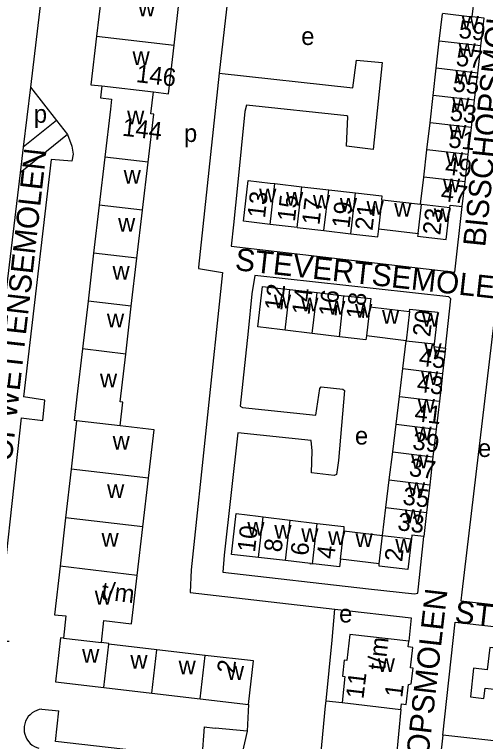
# Model space of a CAD drawing. Extents: x 159902 to 161769, y 383692 to 384875.
# Drawn here: x 161287.3 to 161393, y 384324.5 to 384487.6 of the extents above; entities that cross this region are included whole.
import ezdxf

# ---------------------------------------------------------------- set-up
doc = ezdxf.new("R2010")
doc.units = 0
for name, color, linetype in [('BLT_Basislijn', 7, 'Continuous'), ('BLT_Bebouwing', 7, 'Continuous'), ('BLT_Centroide', 7, 'Continuous'), ('BLT_Huisnummer', 7, 'Continuous'), ('BLT_Huisnummer_ tussenligend', 7, 'Continuous'), ('BLT_Huisnummer_reeks', 7, 'Continuous'), ('BLT_Onderverdeling_panden', 7, 'Continuous'), ('BLT_Straatnaam', 7, 'Continuous')]:
    doc.layers.add(name, color=color, linetype=linetype)

msp = doc.modelspace()

# ---------------------------------------------------------------- linework, layer by layer
at = {"layer": 'BLT_Basislijn'}
for p, q in [((161294.24, 384500), (161290.85, 384471.28)), ((161336.09, 384500), (161333.26, 384474.42)), ((161290.85, 384471.28), (161289.23, 384457.8)), ((161290.85, 384471.28), (161296.72, 384463.85)), ((161296.72, 384463.85), (161289.23, 384457.8)), ((161296.72, 384463.85), (161299.15, 384460.67)), ((161299.15, 384460.67), (161288.54, 384452.1)), ((161289.23, 384457.8), (161288.54, 384452.1)), ((161288.54, 384452.1), (161273.96, 384331.2)), ((161357.23, 384333.57), (161360.85, 384333.19)), ((161293.42, 384331.7), (161297.23, 384331.31)), ((161339.78, 384332.77), (161339.49, 384326.74)), ((161374.02, 384331.65), (161372.88, 384319.36)), ((161329.87, 384327.74), (161332.36, 384327.45)), ((161339.49, 384326.74), (161332.36, 384327.45)), ((161339.49, 384326.74), (161337.1, 384316.46)), ((161383.46, 384325.86), (161380.67, 384301.54)), ((161463.15, 384317.18), (161383.46, 384325.86))]:
    msp.add_line(p, q, dxfattribs=at)
for points in [[(161333.26, 384474.42), (161363.22, 384471.15), (161364.07, 384477.37), (161369.81, 384476.8), (161367.82, 384457.29), (161361.86, 384458.02), (161362.1, 384464.71), (161361.87, 384464.87), (161339.39, 384467.22), (161339.01, 384465.84), (161337.35, 384449.24), (161336.45, 384440.43), (161335.9, 384435.6), (161386.14, 384429.8), (161387.8, 384444.54)], [(161333.26, 384474.42), (161328.56, 384430.9), (161328.61, 384430.62), (161333.96, 384429.73), (161326.96, 384362.94), (161326.68, 384357.85), (161359.22, 384354.18)], [(161299.15, 384460.67), (161300.15, 384458.09), (161300.4, 384456.26), (161300.15, 384454.68), (161295.53, 384455.04), (161289.27, 384401.76)], [(161384.08, 384412.74), (161385.23, 384423.82), (161384.82, 384424.26), (161368.51, 384426.04), (161341.23, 384429.03), (161340.6, 384424.91), (161339.73, 384416.53), (161337.97, 384399.67), (161338.45, 384399.39), (161354.91, 384397.69), (161355.81, 384403.7), (161356.13, 384404.02), (161361, 384403.52), (161361.38, 384403.23), (161360.03, 384387.49), (161359.59, 384384.34), (161359.04, 384384.15), (161353.94, 384384.73), (161354.15, 384389.69), (161353.89, 384392.01), (161337.42, 384393.73), (161334.37, 384366.25), (161334.03, 384362.42), (161366.79, 384358.72), (161377.06, 384357.55), (161377.85, 384357.74), (161379.17, 384370.48)], [(161459.19, 384412.99), (161459.41, 384415.65), (161437.91, 384418.21), (161395.42, 384422.86), (161387.74, 384357.97), (161387.49, 384355.98), (161488.9, 384344.6)], [(161288.75, 384397.06), (161293.59, 384396.45), (161294.07, 384401.08), (161289.27, 384401.76)], [(161288.75, 384397.06), (161283.22, 384346.97), (161286.06, 384346.97)], [(161357.23, 384333.57), (161358.6, 384347.17), (161359.22, 384354.18)], [(161359.22, 384354.18), (161376.36, 384352.21), (161375.82, 384346.94)], [(161383.46, 384325.86), (161386.25, 384351.26), (161481.08, 384340.63)], [(161372.88, 384319.36), (161356.05, 384321.28), (161357.12, 384332.46), (161357.23, 384333.57)], [(161293.42, 384331.7), (161292.83, 384331.6), (161292.26, 384331.42), (161291.72, 384331.17), (161291.21, 384330.85), (161290.76, 384330.46), (161290.36, 384330.02), (161290.02, 384329.52), (161289.76, 384328.99), (161289.56, 384328.43), (161289.44, 384327.84), (161289.4, 384327.24), (161289.45, 384326.65), (161289.57, 384326.06), (161289.77, 384325.5), (161290.04, 384324.97), (161290.38, 384324.48), (161290.78, 384324.03), (161291.24, 384323.65), (161291.74, 384323.33), (161292.29, 384323.08), (161292.73, 384322.94)], [(161329.87, 384327.74), (161329.33, 384320.72), (161296.47, 384324.43), (161297.23, 384331.31)]]:
    msp.add_lwpolyline(points, dxfattribs=at)
at = {"layer": 'BLT_Bebouwing'}
for p, q in [((161390.06, 384487.11), (161390.96, 384494.84)), ((161306.96, 384493.63), (161305.69, 384482.74)), ((161323.09, 384480.71), (161324.36, 384491.6)), ((161382.67, 384481.64), (161383.37, 384487.74)), ((161381.97, 384475.53), (161382.67, 384481.64)), ((161381.28, 384469.43), (161381.97, 384475.53)), ((161390.59, 384468.36), (161391.31, 384474.47)), ((161317.9, 384465.28), (161318.47, 384470.21)), ((161380.58, 384463.32), (161381.28, 384469.43)), ((161389.88, 384462.26), (161390.59, 384468.36)), ((161308.8, 384466.34), (161307.55, 384455.58)), ((161379.88, 384457.21), (161380.58, 384463.32)), ((161389.16, 384456.15), (161389.88, 384462.26)), ((161379.18, 384451.11), (161379.88, 384457.21)), ((161307.55, 384455.58), (161306.29, 384444.82)), ((161388.45, 384450.05), (161389.16, 384456.15)), ((161316.01, 384443.69), (161317.27, 384454.45)), ((161378.48, 384445), (161379.18, 384451.11)), ((161345.76, 384449.65), (161351.8, 384448.96)), ((161351.8, 384448.96), (161357.84, 384448.27)), ((161387.8, 384444.54), (161388.45, 384450.05)), ((161357.84, 384448.27), (161363.88, 384447.58)), ((161369.85, 384445.99), (161378.48, 384445)), ((161306.29, 384444.82), (161305.04, 384434.06)), ((161314.75, 384432.93), (161316.01, 384443.69)), ((161350.73, 384439.77), (161344.69, 384440.45)), ((161350.73, 384439.77), (161356.77, 384439.09)), ((161356.77, 384439.09), (161362.82, 384438.41)), ((161369.09, 384439.48), (161377.9, 384438.44)), ((161305.04, 384434.06), (161303.78, 384423.3)), ((161313.5, 384422.16), (161314.75, 384432.93)), ((161349.13, 384425.86), (161355.24, 384425.18)), ((161355.24, 384425.18), (161361.26, 384424.5)), ((161361.26, 384424.5), (161361.35, 384424.49)), ((161361.35, 384424.49), (161367.27, 384423.83)), ((161303.78, 384423.3), (161302.52, 384412.54)), ((161367.27, 384423.83), (161367.05, 384421.97)), ((161312.24, 384411.4), (161313.5, 384422.16)), ((161367.05, 384421.97), (161376, 384420.93)), ((161354.13, 384416.02), (161348.03, 384416.76)), ((161360.23, 384415.28), (161354.13, 384416.02)), ((161375.24, 384414.38), (161366.29, 384415.47)), ((161374.48, 384408.14), (161375.24, 384414.38)), ((161302.52, 384412.54), (161301.27, 384401.77)), ((161310.99, 384400.64), (161312.24, 384411.4)), ((161384.08, 384412.74), (161383.41, 384407.05)), ((161373.72, 384401.9), (161374.48, 384408.14)), ((161301.27, 384401.77), (161300.65, 384396.5)), ((161372.96, 384395.66), (161373.72, 384401.9)), ((161382.68, 384400.81), (161381.96, 384394.56)), ((161301.21, 384396.43), (161299.97, 384385.54)), ((161301.21, 384396.43), (161300.65, 384396.5)), ((161372.2, 384389.42), (161372.96, 384395.66)), ((161381.96, 384394.56), (161381.24, 384388.32)), ((161371.44, 384383.18), (161372.2, 384389.42)), ((161381.24, 384388.32), (161380.51, 384382.07)), ((161299.97, 384385.54), (161298.73, 384374.65)), ((161316.11, 384372.62), (161317.38, 384383.51)), ((161370.68, 384376.93), (161371.44, 384383.18)), ((161380.51, 384382.07), (161379.79, 384375.83)), ((161369.92, 384370.69), (161370.68, 384376.93)), ((161379.79, 384375.83), (161379.17, 384370.48)), ((161298.73, 384374.65), (161297.49, 384363.76)), ((161343.1, 384374.87), (161349.16, 384374.13)), ((161349.16, 384374.13), (161355.21, 384373.4)), ((161314.84, 384361.73), (161316.11, 384372.62)), ((161361.21, 384371.75), (161369.92, 384370.69)), ((161348.11, 384365.04), (161342.05, 384365.74)), ((161369.16, 384364.34), (161360.44, 384365.4)), ((161298.79, 384352.62), (161298.24, 384347.63)), ((161306.77, 384346.64), (161307.35, 384351.57)), ((161319.26, 384345.04), (161308.43, 384346.3)), ((161330.09, 384343.78), (161319.26, 384345.04)), ((161307.3, 384336.55), (161318.13, 384335.29)), ((161318.13, 384335.29), (161328.96, 384334.03)), ((161328.96, 384334.03), (161339.78, 384332.77)), ((161360.85, 384333.19), (161374.02, 384331.65))]:
    msp.add_line(p, q, dxfattribs=at)
for points in [[(161392.02, 384480.57), (161392.75, 384486.79), (161390.06, 384487.11)], [(161305.69, 384482.74), (161304.42, 384471.81), (161306.88, 384471.56)], [(161318.47, 384470.21), (161321.82, 384469.82), (161323.09, 384480.71)], [(161391.31, 384474.47), (161391.62, 384477.09), (161392.02, 384480.57)], [(161306.88, 384471.56), (161306.57, 384468.93), (161309.07, 384468.63), (161308.8, 384466.34)], [(161317.27, 384454.45), (161318.52, 384465.21), (161317.9, 384465.28)], [(161344.69, 384440.45), (161338.66, 384441.25), (161339.71, 384450.34), (161344.67, 384449.77), (161345.76, 384449.65)], [(161363.88, 384447.58), (161369.79, 384446.9), (161369.69, 384446.01), (161369.85, 384445.99)], [(161377.9, 384438.44), (161377.8, 384437.84), (161384.2, 384437.09), (161385.05, 384444.22)], [(161385.05, 384444.22), (161385.12, 384444.81), (161387.8, 384444.54)], [(161362.82, 384438.41), (161368.85, 384437.74), (161369.09, 384439.48)], [(161348.03, 384416.76), (161346.88, 384416.9), (161341.92, 384417.51), (161342.97, 384426.55), (161349.13, 384425.86)], [(161376, 384420.93), (161376.06, 384421.49), (161382.32, 384420.82), (161381.48, 384413.66)], [(161366.29, 384415.47), (161366.18, 384414.56), (161360.23, 384415.28)], [(161381.48, 384413.66), (161381.41, 384413.07), (161384.08, 384412.74)], [(161383.41, 384407.05), (161383.21, 384405.37), (161382.68, 384400.81)], [(161310.98, 384395.3), (161311.6, 384400.57), (161310.99, 384400.64)], [(161317.38, 384383.51), (161318.65, 384394.4), (161310.98, 384395.3)], [(161342.05, 384365.74), (161335.99, 384366.44), (161337.06, 384375.61), (161342.02, 384375), (161343.1, 384374.87)], [(161355.21, 384373.4), (161361.23, 384372.67), (161361.21, 384371.75)], [(161379.17, 384370.48), (161376.5, 384370.77), (161376.4, 384369.91)], [(161376.4, 384369.91), (161375.6, 384363.02), (161369.16, 384363.78), (161369.16, 384364.34)], [(161354.17, 384364.32), (161353.71, 384364.25), (161353.74, 384364.39), (161348.11, 384365.04)], [(161360.44, 384365.4), (161360.23, 384363.65), (161354.36, 384364.34), (161354.17, 384364.32)], [(161297.49, 384363.76), (161296.26, 384352.9), (161298.79, 384352.62)], [(161307.35, 384351.57), (161313.56, 384350.84), (161314.84, 384361.73)], [(161375.82, 384346.94), (161362.6, 384348.49), (161361.89, 384342.63), (161361.3, 384342.68), (161360.89, 384339.1), (161361.43, 384339.03), (161360.85, 384333.19)], [(161298.24, 384347.63), (161297.57, 384347.7), (161296.47, 384337.81), (161307.3, 384336.55)], [(161308.43, 384346.3), (161308.45, 384346.44), (161306.77, 384346.64)], [(161374.02, 384331.65), (161374.16, 384332.92), (161375.21, 384332.78), (161375.78, 384337.27), (161376.36, 384337.35), (161376.77, 384340.87), (161376.18, 384340.96), (161376.69, 384345.56), (161375.67, 384345.67), (161375.82, 384346.94)], [(161400.1, 384344.84), (161393.99, 384345.52), (161393.42, 384340.56), (161390.38, 384340.91), (161389.64, 384334.44), (161392.65, 384334.1), (161392.95, 384336.43), (161399.06, 384335.73)], [(161339.78, 384332.77), (161340.92, 384342.52), (161330.09, 384343.78)]]:
    msp.add_lwpolyline(points, dxfattribs=at)
at = {"layer": 'BLT_Onderverdeling_panden'}
for p, q in [((161383.38, 384487.87), (161390.06, 384487.11)), ((161305.69, 384482.74), (161323.09, 384480.71)), ((161392.02, 384480.57), (161382.67, 384481.64)), ((161391.31, 384474.47), (161381.97, 384475.53)), ((161306.88, 384471.56), (161318.47, 384470.21)), ((161390.59, 384468.36), (161381.28, 384469.43)), ((161389.88, 384462.26), (161380.58, 384463.32)), ((161389.16, 384456.15), (161379.88, 384457.21)), ((161317.27, 384454.45), (161307.55, 384455.58)), ((161388.45, 384450.05), (161379.18, 384451.11)), ((161344.69, 384440.45), (161345.76, 384449.65)), ((161350.73, 384439.77), (161351.8, 384448.96)), ((161356.77, 384439.09), (161357.84, 384448.27)), ((161362.82, 384438.41), (161363.88, 384447.58)), ((161369.09, 384439.48), (161369.85, 384445.99)), ((161316.01, 384443.69), (161306.29, 384444.82)), ((161377.9, 384438.44), (161378.66, 384444.98)), ((161378.66, 384444.98), (161378.48, 384445)), ((161385.05, 384444.22), (161378.66, 384444.98)), ((161314.75, 384432.93), (161305.04, 384434.06)), ((161348.03, 384416.76), (161349.13, 384425.86)), ((161354.13, 384416.02), (161355.24, 384425.18)), ((161361.24, 384424.39), (161361.26, 384424.5)), ((161361.24, 384424.39), (161361.35, 384424.49)), ((161313.5, 384422.16), (161303.78, 384423.3)), ((161360.23, 384415.28), (161361.24, 384424.39)), ((161367.05, 384421.97), (161366.29, 384415.47)), ((161376, 384420.93), (161375.24, 384414.38)), ((161375.24, 384414.38), (161381.48, 384413.66)), ((161312.24, 384411.4), (161302.52, 384412.54)), ((161374.48, 384408.14), (161383.41, 384407.05)), ((161373.72, 384401.9), (161382.68, 384400.81)), ((161310.98, 384395.3), (161301.21, 384396.43)), ((161372.96, 384395.66), (161381.96, 384394.56)), ((161372.2, 384389.42), (161381.24, 384388.32)), ((161317.38, 384383.51), (161299.97, 384385.54)), ((161371.44, 384383.18), (161380.51, 384382.07)), ((161370.68, 384376.93), (161379.79, 384375.83)), ((161316.11, 384372.62), (161298.73, 384374.65)), ((161342.05, 384365.74), (161343.1, 384374.87)), ((161348.11, 384365.04), (161349.16, 384374.13)), ((161354.17, 384364.32), (161355.21, 384373.4)), ((161360.44, 384365.4), (161361.21, 384371.75)), ((161369.16, 384364.34), (161369.92, 384370.69)), ((161369.92, 384370.69), (161376.4, 384369.91)), ((161314.84, 384361.73), (161297.49, 384363.76)), ((161298.24, 384347.63), (161306.77, 384346.64)), ((161307.3, 384336.55), (161308.43, 384346.3)), ((161318.13, 384335.29), (161319.26, 384345.04)), ((161328.96, 384334.03), (161330.09, 384343.78))]:
    msp.add_line(p, q, dxfattribs=at)

# ---------------------------------------------------------------- texts
at = {"layer": 'BLT_Centroide'}
for s, p in [('w', (161315.02, 384487.19)), ('w', (161387.71, 384484.22)), ('e', (161351.66, 384480.76)), ('w', (161387, 384478.06)), ('w', (161313.76, 384476.28)), ('w', (161386.29, 384471.94)), ('w', (161385.58, 384465.84)), ('p', (161291.6, 384463.31)), ('w', (161312.55, 384462.95)), ('p', (161325.32, 384458.99)), ('w', (161384.88, 384459.75)), ('w', (161384.16, 384453.62)), ('w', (161311.78, 384449.64)), ('w', (161383.48, 384447.66)), ('w', (161342.2, 384445.42)), ('w', (161348.25, 384444.72)), ('w', (161354.28, 384444.03)), ('w', (161360.33, 384443.33)), ('w', (161366.33, 384442.66)), ('w', (161372.54, 384442.22)), ('w', (161381.42, 384441.03)), ('w', (161310.52, 384438.88)), ('w', (161309.27, 384428.11)), ('w', (161345.53, 384421.66)), ('w', (161351.64, 384420.95)), ('w', (161357.69, 384420.25)), ('w', (161363.75, 384419.53)), ('w', (161369.81, 384418.19)), ('w', (161308.02, 384417.36)), ('w', (161378.78, 384417.58)), ('w', (161379.32, 384410.72)), ('w', (161306.45, 384403.94)), ('w', (161378.57, 384404.47)), ('w', (161377.82, 384398.22)), ('w', (161377.09, 384392)), ('e', (161363.72, 384391.09)), ('w', (161309.3, 384389.97)), ('e', (161391.35, 384388.3)), ('w', (161376.34, 384385.75)), ('w', (161308.05, 384379.09)), ('w', (161375.61, 384379.5)), ('w', (161374.88, 384373.44)), ('w', (161339.55, 384370.67)), ('w', (161345.61, 384369.95)), ('w', (161351.66, 384369.22)), ('w', (161306.8, 384368.19)), ('w', (161357.7, 384368.52)), ('w', (161363.85, 384368.06)), ('w', (161372.78, 384366.84)), ('w', (161305.3, 384355.19)), ('e', (161360.16, 384351.16)), ('w', (161302.45, 384342.12)), ('w', (161313.28, 384340.78)), ('w', (161368.84, 384340.06)), ('w', (161324.11, 384339.53)), ('w', (161334.94, 384338.28))]:
    msp.add_text(s, height=4, dxfattribs=at).set_placement(p)
at = {"layer": 'BLT_Huisnummer'}
for s, rotation, p in [('59', 353.4736, (161386.87, 384482.37)), ('55', 353.4797, (161385.52, 384470.37)), ('51', 353.4793, (161384.57, 384457.81)), ('47', 353.182, (161382.85, 384445.81)), ('13', 83.3552, (161343.5, 384441.77)), ('17', 83.2999, (161355.74, 384440.25)), ('21', 83.2937, (161367.65, 384438.99)), ('23', 83.5873, (161382.88, 384437.99)), ('12', 83.0677, (161347.36, 384421)), ('16', 83.394, (161359.54, 384419.66)), ('20', 83.3065, (161380.62, 384415.13)), ('45', 353.0654, (161377.93, 384408.83)), ('41', 353.0679, (161376.96, 384396.38)), ('37', 353.0678, (161375.72, 384384.05)), ('33', 353.1049, (161373.14, 384371.89)), ('10', 83.3547, (161341.25, 384366.77)), ('4', 83.4265, (161359.06, 384365.27)), ('2', 83.3408, (161374.32, 384364.65))]:
    msp.add_text(s, height=4, rotation=rotation, dxfattribs=at).set_placement(p)
at = {"layer": 'BLT_Huisnummer_ tussenligend'}
for s, rotation, p in [('57', 353.4797, (161386.27, 384476.14)), ('53', 353.4793, (161384.89, 384463.82)), ('49', 353.182, (161383.81, 384451.77)), ('15', 83.3552, (161350.22, 384441)), ('19', 83.2999, (161362.47, 384439.49)), ('14', 83.0677, (161353.51, 384420.02)), ('18', 83.394, (161365.69, 384419.1)), ('43', 353.0679, (161377.48, 384402.97)), ('39', 353.0678, (161376.5, 384390.01)), ('35', 353.1049, (161374.29, 384377.65)), ('8', 83.3547, (161347.22, 384366.8)), ('6', 83.4265, (161353.19, 384366.01))]:
    msp.add_text(s, height=4, rotation=rotation, dxfattribs=at).set_placement(p)
at = {"layer": 'BLT_Huisnummer_reeks'}
for s, rotation, p in [('146', 353.3455, (161314.44, 384472.45)), ('144', 353.3463, (161311.32, 384460.43)), ('t/m', 352.9995, (161306.6, 384356.39)), ('t/m', 83.6748, (161370.48, 384340.29)), ('2', 83.3502, (161336.69, 384339.6)), ('11', 83.1264, (161365.62, 384333.88)), ('1', 82.787, (161374.33, 384334.17))]:
    msp.add_text(s, height=4, rotation=rotation, dxfattribs=at).set_placement(p)
at = {"layer": 'BLT_Straatnaam'}
for s, rotation, p in [('BISSCHOPSMOLEN', 84.0322, (161392.96, 384435.31)), ('OPWETTENSEMOLEN', 83.6113, (161286.62, 384387.12)), ('STEVERTSEMOLEN', 353.7396, (161336.64, 384430.25)), ('BISSCHOPSMOLEN', 83.4585, (161377.37, 384296.07)), ('STEVERTSEMOLEN', 353.6054, (161385.96, 384351.12))]:
    msp.add_text(s, height=5, rotation=rotation, dxfattribs=at).set_placement(p)

doc.saveas('drawing.dxf')
